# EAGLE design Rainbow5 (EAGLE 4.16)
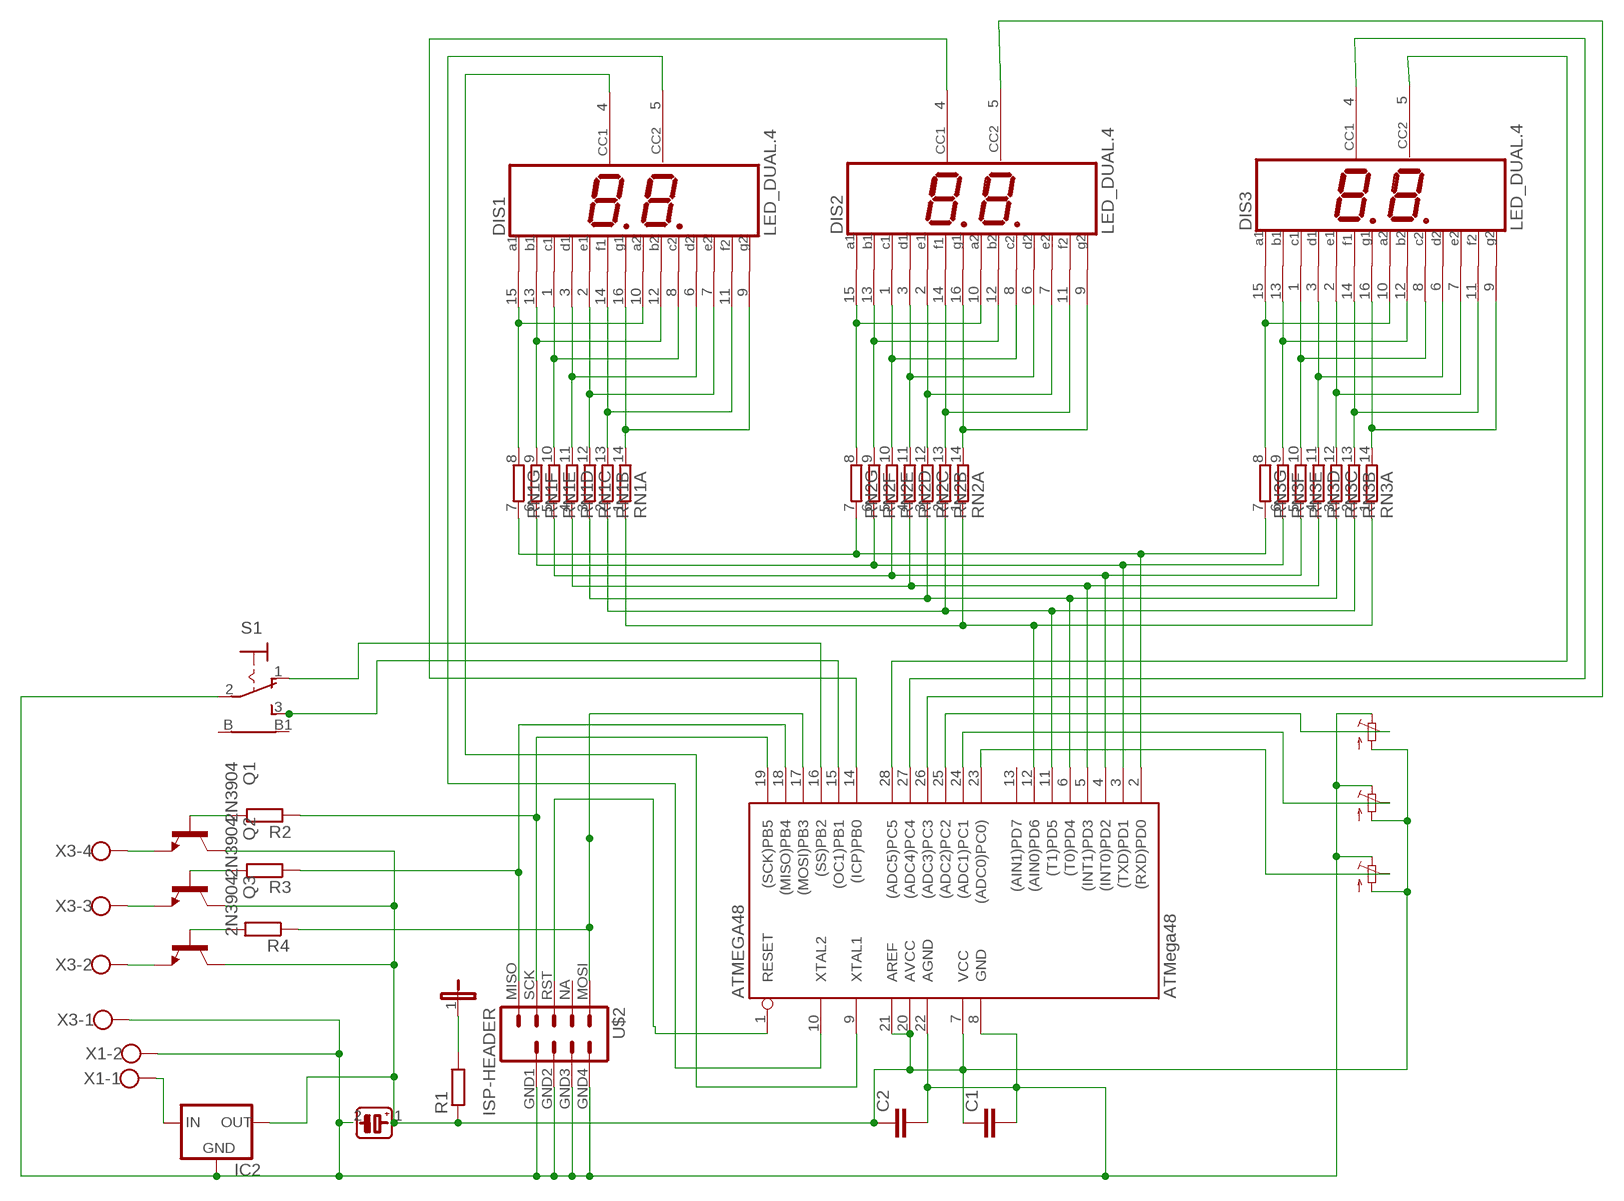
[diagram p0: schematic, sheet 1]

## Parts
ATMEGA48  ATMega48  AT90S4433P  [DIL28-3]
C1  C-EU025-024X044  [C025-024X044]
C2  C-EU025-024X044  [C025-024X044]
DIS1  LED_DUAL.4  [LED_DUAL.4]
DIS2  LED_DUAL.4  [LED_DUAL.4]
DIS3  LED_DUAL.4  [LED_DUAL.4]
IC2  78MXXS  [78MXXS]
Q1  2N3904  [TO92]
Q2  2N3904  [TO92]
Q3  2N3904  [TO92]
R1  R-EU_0204/7  [0204/7]
R2  R-EU_0204/7  [0204/7]
R3  R-EU_0204/7  [0204/7]
R4  R-EU_0204/7  [0204/7]
RN1  7R-N  [DIL14]
RN2  7R-N  [DIL14]
RN3  7R-N  [DIL14]
S1  9070-1W  [9070-1W]
U$1  CAPACITOR_TANTALUM_RADIAL_10UF  [CAPACITOR_TANTALUM_RADIAL_10UF]
U$2  ISP-HEADER  [ISP-HEADER]
U$3  JUMPER1  [JUMPER1]
U$13  POTENTIOMETER_VERTICAL_PCB_.25  [POTENTIOMETER_VERTICAL_PCB_.25]
U$14  POTENTIOMETER_VERTICAL_PCB_.25  [POTENTIOMETER_VERTICAL_PCB_.25]
U$15  POTENTIOMETER_VERTICAL_PCB_.25  [POTENTIOMETER_VERTICAL_PCB_.25]
X1  W237-102  [W237-102]
X3  W237-4  [W237-4]

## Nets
N$1: DIS1.10(A2) DIS1.15(A1) RN1.8
N$2: DIS1.12(B2) DIS1.13(B1) RN1.9
N$3: DIS1.1(C1) DIS1.8(C2) RN1.10
N$4: DIS1.3(D1) DIS1.6(D2) RN1.11
N$5: DIS1.2(E1) DIS1.7(E2) RN1.12
N$6: DIS1.11(F2) DIS1.14(F1) RN1.13
N$7: ATMEGA48.19((SCK)PB5) R2.1 U$2.SCK
N$8: DIS2.10(A2) DIS2.15(A1) RN2.8
N$9: DIS2.12(B2) DIS2.13(B1) RN2.9
N$10: DIS2.1(C1) DIS2.8(C2) RN2.10
N$11: DIS2.3(D1) DIS2.6(D2) RN2.11
N$12: DIS2.2(E1) DIS2.7(E2) RN2.12
N$13: DIS2.11(F2) DIS2.14(F1) RN2.13
N$14: ATMEGA48.18((MISO)PB4) R3.1 U$2.MISO
N$15: ATMEGA48.2((RXD)PD0) RN1.7 RN2.7 RN3.7
N$16: DIS3.1(C1) DIS3.8(C2) RN3.10
N$17: ATMEGA48.7(VCC) ATMEGA48.20(AVCC) ATMEGA48.21(AREF) C1.1 C2.1 IC2.OUT Q1.1(C) Q2.1(C) Q3.1(C) R1.1 U$1.1 U$13.1 U$14.1 U$15.1
N$18: DIS1.9(G2) DIS1.16(G1) RN1.14
N$19: R1.2 U$3.1
N$20: DIS2.9(G2) DIS2.16(G1) RN2.14
N$21: ATMEGA48.3((TXD)PD1) RN1.6 RN2.6 RN3.6
N$22: DIS3.10(A2) DIS3.15(A1) RN3.8
N$23: DIS3.12(B2) DIS3.13(B1) RN3.9
N$24: ATMEGA48.4((INT0)PD2) RN1.5 RN2.5 RN3.5
N$25: DIS3.3(D1) DIS3.6(D2) RN3.11
N$26: DIS3.2(E1) DIS3.7(E2) RN3.12
N$27: DIS3.11(F2) DIS3.14(F1) RN3.13
N$28: DIS3.9(G2) DIS3.16(G1) RN3.14
N$29: ATMEGA48.5((INT1)PD3) RN1.4 RN2.4 RN3.4
N$30: ATMEGA48.6((T0)PD4) RN1.3 RN2.3 RN3.3
N$31: ATMEGA48.11((T1)PD5) RN1.2 RN2.2 RN3.2
N$32: ATMEGA48.8(GND) ATMEGA48.22(AGND) C1.2 C2.2 IC2.GND S1.2(P) U$1.2 U$2.GND1 U$2.GND2 U$2.GND3 U$2.GND4 U$13.3 U$14.3 U$15.3 X1.2 X3.1
N$33: Q1.3(E) X3.4
N$34: ATMEGA48.25((ADC2)PC2) U$13.2
N$35: ATMEGA48.12((AIN0)PD6) RN1.1 RN2.1 RN3.1
N$36: ATMEGA48.24((ADC1)PC1) U$14.2
N$37: ATMEGA48.23((ADC0)PC0)) U$15.2
N$38: ATMEGA48.9(XTAL1) DIS1.4(CC1)
N$39: ATMEGA48.10(XTAL2) DIS1.5(CC2)
N$40: ATMEGA48.14((ICP)PB0) DIS2.4(CC1)
N$41: ATMEGA48.26((ADC3)PC3) DIS2.5(CC2)
N$42: ATMEGA48.27((ADC4)PC4) DIS3.4(CC1)
N$43: ATMEGA48.28((ADC5)PC5) DIS3.5(CC2)
N$44: ATMEGA48.15((OC1)PB1) S1.3(S)
N$45: ATMEGA48.16((SS)PB2) S1.1(O)
N$46: ATMEGA48.17((MOSI)PB3) R4.1 U$2.MOSI
N$47: ATMEGA48.1(RESET) U$2.RST(RESET)
N$48: Q2.3(E) X3.3
N$49: Q3.3(E) X3.2
N$50: Q1.2(B) R2.2
N$51: Q2.2(B) R3.2
N$52: Q3.2(B) R4.2
N$53: IC2.IN X1.1
Unconnected: ATMEGA48.13((AIN1)PD7) S1.B S1.B1 U$2.NA

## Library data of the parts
ATMEGA48 = atmel:AT90S4433: MICROCONTROLLER 4 Kbytes FLASH 128 bytes SRAM 256 bytes EEPROM UART 6-channel 10 bit ADC
C1 C2 = rcl:C-EU: CAPACITOR, European symbol
DIS1-DIS3 = Williams:LED_DUAL.4: LED DISPLAY 2-Digit, 7 segment, decimal point right, .4"
IC2 = v-reg:78MXXS: VOLTAGE REGULATOR
Q1-Q3 = transistor-npn:2N3904: NPN Transistor
R1-R4 = rcl:R-EU_: RESISTOR, European symbol
RN1-RN3 = resistor-dil:7R-N: DIL RESISTOR
S1 = SWITCH:9070-1W: TOGGLE SWITCH Marquardt
U$1 = Williams:CAPACITOR_TANTALUM_RADIAL_10UF
U$2 = Williams:ISP-HEADER
U$3 = Williams:JUMPER1
U$13-U$15 = Williams:POTENTIOMETER_VERTICAL_PCB_.25
X1 = con-wago-500:W237-102: WAGO SCREW CLAMP
X3 = con-wago-500:W237-4: WAGO SCREW CLAMP

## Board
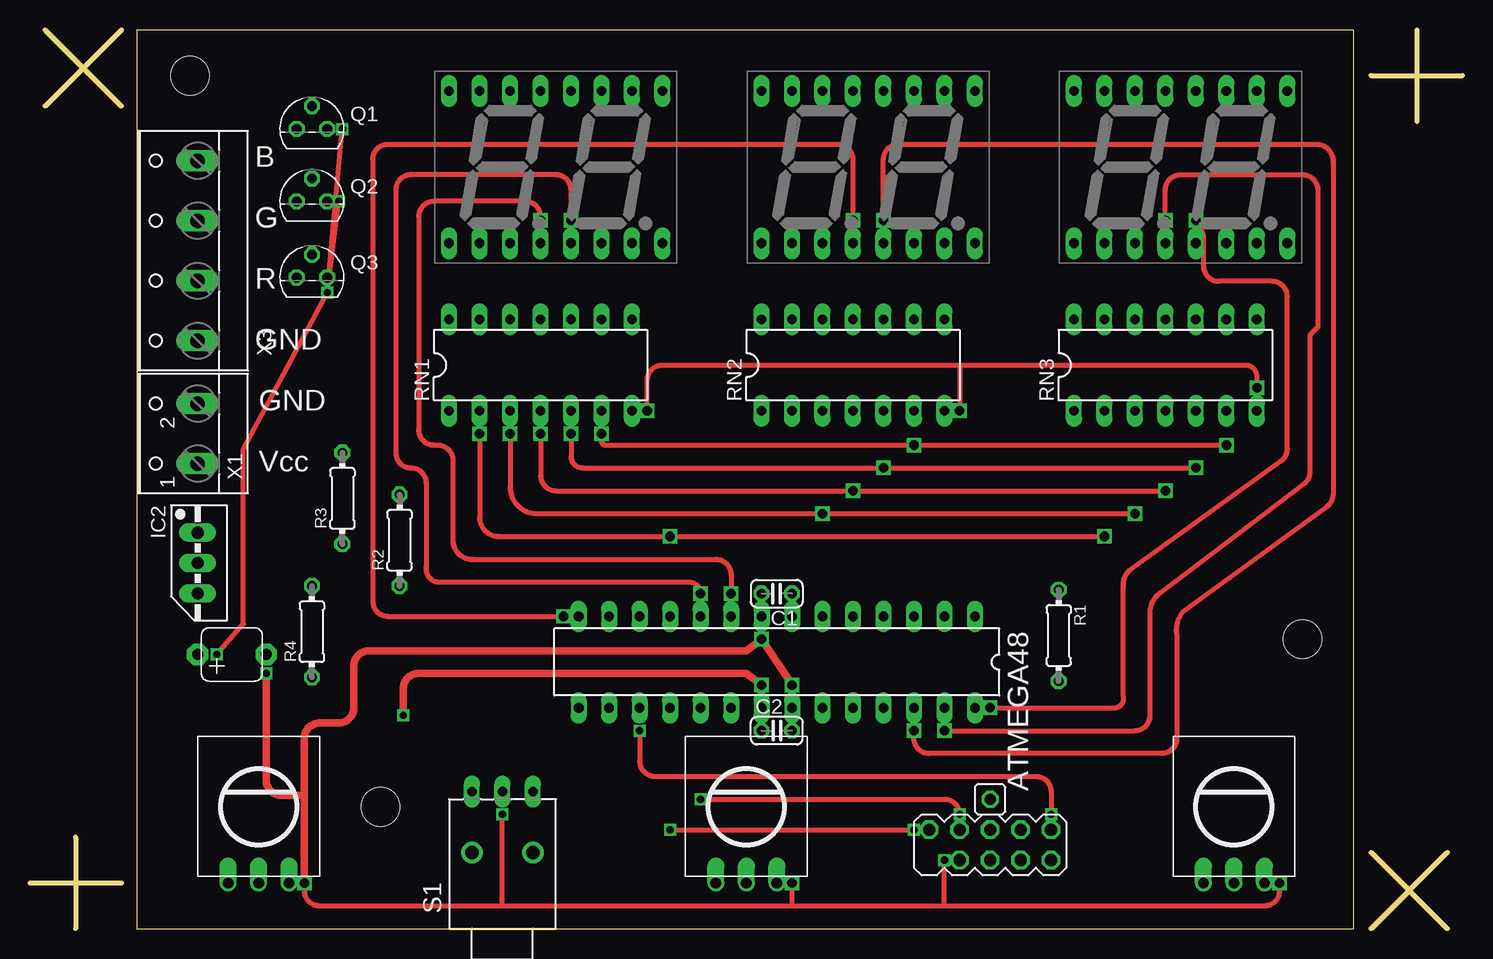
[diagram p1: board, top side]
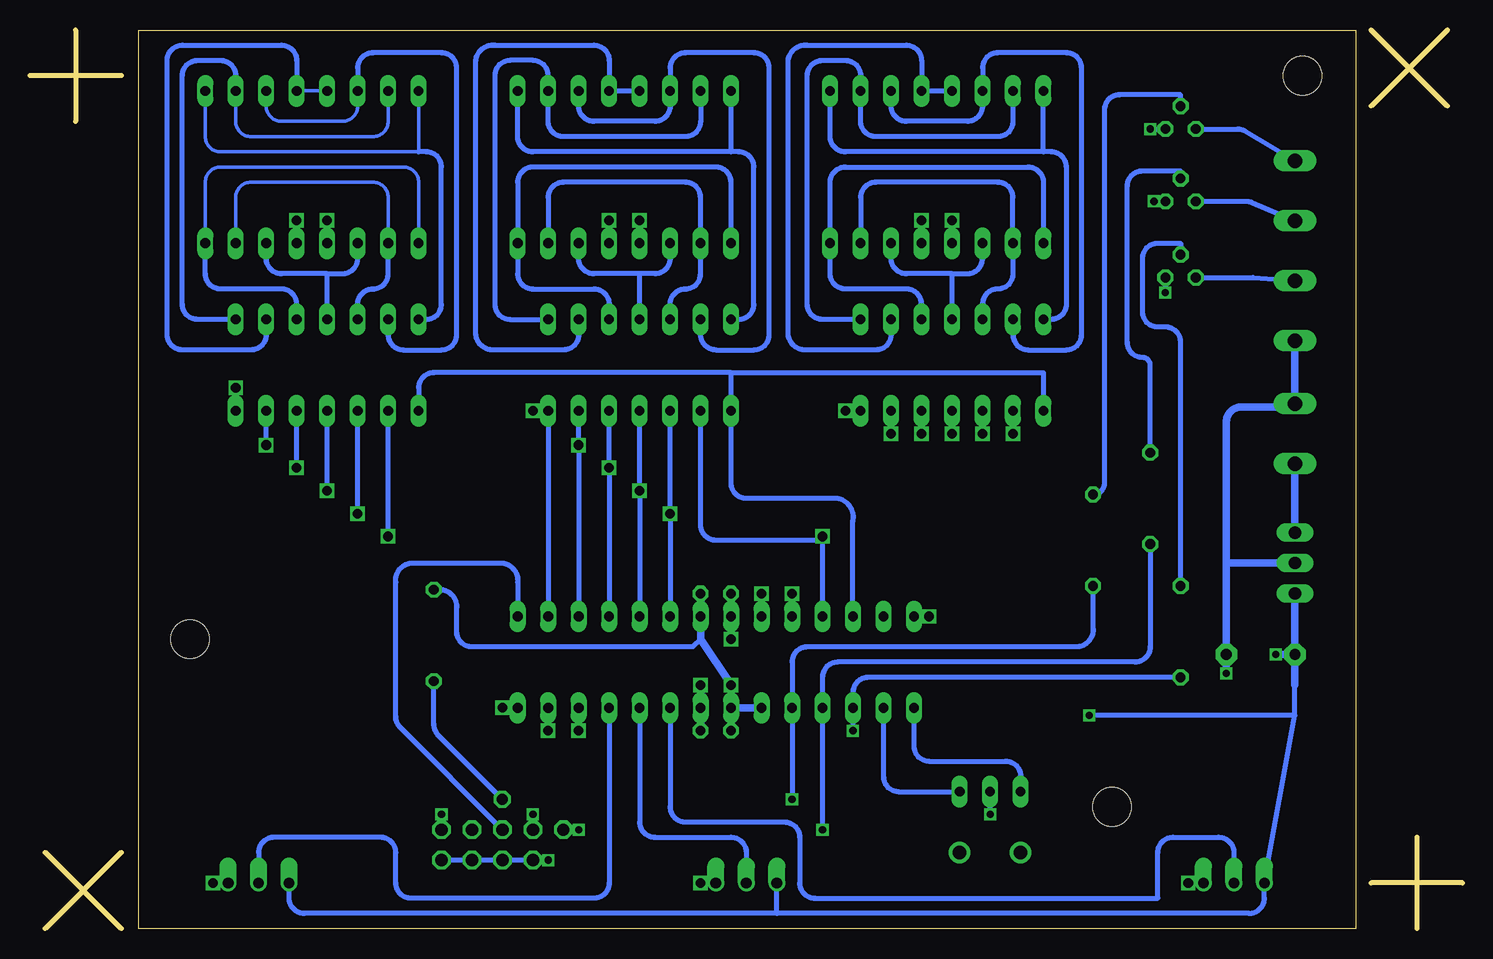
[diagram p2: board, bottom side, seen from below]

Size 119.38 x 74.93 mm. Coordinates in mm from the lower left corner, seen from the top.
Outline: 1.27,74.93 7.62,68.58
Outline: 1.27,68.58 7.62,74.93
Outline: 111.76,6.35 118.11,0
Outline: 111.76,0 118.11,6.35
Outline: 0,3.81 7.62,3.81
Outline: 3.81,7.62 3.81,0
Outline: 115.57,74.93 115.57,67.31
Outline: 111.76,71.12 119.38,71.12
Outline: 8.9,0.01 110.33,0.01 110.33,74.92 8.9,74.92 8.9,0.01
Copper layers (1*16): Top 0.035mm / dielectric 1.5mm / Bottom 0.035mm
Design rules "default": minimum track width 10mil, minimum drill 24mil, track to track 8mil, track to pad 8mil, pad to pad 8mil, via to via 8mil, smd to smd 8mil, copper to edge 40mil, drill to drill 8mil, minimum pad ring 10mil, minimum via ring 8mil, stop-mask expansion 4mil, vias tented up to drill 0mil, thermal gap 10mil
Holes 3.2 mm at 29.21,10.16 106.05,24.13 13.34,71.12

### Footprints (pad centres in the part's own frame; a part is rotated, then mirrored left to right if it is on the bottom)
DIL28-3 = drill 0.813 long: 1 -16.51,-3.81; 2 -13.97,-3.81; 3 -11.43,-3.81; 4 -8.89,-3.81; 5 -6.35,-3.81; 6 -3.81,-3.81; 7 -1.27,-3.81; 8 1.27,-3.81; 9 3.81,-3.81; 10 6.35,-3.81; 11 8.89,-3.81; 12 11.43,-3.81; 13 13.97,-3.81; 14 16.51,-3.81; 15 16.51,3.81; 16 13.97,3.81; 17 11.43,3.81; 18 8.89,3.81; 19 6.35,3.81; 20 3.81,3.81; 21 1.27,3.81; 22 -1.27,3.81; 23 -3.81,3.81; 24 -6.35,3.81; 25 -8.89,3.81; 26 -11.43,3.81; 27 -13.97,3.81; 28 -16.51,3.81
C025-024X044 = drill 0.813 octagon: 1 -1.27,0; 2 1.27,0
LED_DUAL.4 = drill 0.813 long: 1 -8.89,-6.35; 2 -6.35,-6.35; 3 -3.81,-6.35; 4 -1.27,-6.35; 5 1.27,-6.35; 6 3.81,-6.35; 7 6.35,-6.35; 8 8.89,-6.35; 9 8.89,6.35; 10 6.35,6.35; 11 3.81,6.35; 12 1.27,6.35; 13 -1.27,6.35; 14 -3.81,6.35; 15 -6.35,6.35; 16 -8.89,6.35
78MXXS = drill 1.016 long: GND 0,-2.54; IN -2.54,-2.54; OUT 2.54,-2.54
TO92 = drill 0.813 octagon: 1 1.27,0; 2 0,1.905; 3 -1.27,0
0204/7 = drill 0.813 octagon: 1 -3.81,0; 2 3.81,0
DIL14 = drill 0.813 long: 1 -7.62,-3.81; 2 -5.08,-3.81; 3 -2.54,-3.81; 4 0,-3.81; 5 2.54,-3.81; 6 5.08,-3.81; 7 7.62,-3.81; 8 7.62,3.81; 9 5.08,3.81; 10 2.54,3.81; 11 0,3.81; 12 -2.54,3.81; 13 -5.08,3.81; 14 -7.62,3.81
9070-1W = drill 0.813 long: 1 5.08,-2.54; 2 5.08,0; 3 5.08,2.54 | drill 1.118 pad 1.778 round: B 0,-2.54; B1 0,2.54
CAPACITOR_TANTALUM_RADIAL_10UF = drill 0.9 pad 1.778 octagon: 1 -2.54,0; 2 3.175,0
ISP-HEADER = drill 1.016 octagon: GND1 -2.54,-1.27; GND2 0,-1.27; GND3 2.54,-1.27; GND4 5.08,-1.27; MISO -5.08,1.27; MOSI 5.08,1.27; NA 2.54,1.27; RST 0,1.27; SCK -2.54,1.27
JUMPER1 = drill 0.914 octagon: 1 0,0
POTENTIOMETER_VERTICAL_PCB_.25 = drill 0.9 pad 1.422 offset: 1 -2.54,-6.35; 2 0,-6.35; 3 2.54,-6.35
W237-102 = drill 1.194 long: 1 -2.5,-1.27; 2 2.5,-1.27
W237-4 = drill 1.194 long: 1 -7.5,-1.27; 2 -2.5,-1.27; 3 2.5,-1.27; 4 7.5,-1.27

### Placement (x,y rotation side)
ATMEGA48  62.23,22.23 180 top
C1  62.23,27.94 180 top
C2  62.23,16.51 0 top
DIS1  43.81,63.5 0 top
DIS2  69.85,63.5 0 top
DIS3  95.89,63.5 0 top
IC2  16.51,30.48 270 top
Q1  23.5,66.67 0 top
Q2  23.5,60.64 0 top
Q3  23.5,54.29 0 top
R1  85.72,24.45 270 top
R2  30.8,32.38 90 top
R3  26.04,35.88 90 top
R4  23.5,24.77 90 top
RN1  42.55,46.99 0 top
RN2  68.58,46.99 0 top
RN3  94.61,46.99 0 top
S1  39.37,6.35 90 top
U$1  16.51,22.86 0 top
U$2  80.01,6.99 0 top
U$3  80.01,10.79 90 top
U$13  100.33,10.16 0 top
U$14  59.69,10.16 0 top
U$15  19.05,10.16 0 top
X1  12.7,41.27 90 top
X3  12.7,56.52 90 top

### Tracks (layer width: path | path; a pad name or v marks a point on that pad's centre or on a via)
N$1
  Bottom 0.406: RN1.8 53.34,50.8 arc90 54.61,52.07 54.61,71.12 arc90 53.34,72.39 51.44,72.39 arc90 50.16,71.12 DIS1.10 50.16,67.31 arc-90 48.9,66.04 38.73,66.04 arc-90 37.47,67.31 DIS1.15
N$2
  Bottom 0.406: DIS1.13 DIS1.12 45.09,72.39 arc-90 46.36,73.66 54.61,73.66 arc-90 56.2,72.39 56.2,49.53 arc-90 54.61,48.26 48.9,48.26 arc-90 47.62,49.53 RN1.9
N$3
  Bottom 0.406: DIS1.1 34.92,62.23 arc-90 36.2,63.5 51.44,63.5 arc-90 52.7,62.23 DIS1.8 52.7,54.61 arc-90 51.44,53.34 46.36,53.34 arc90 45.09,52.07 RN1.10
N$4
  Bottom 0.406: 42.55,54.61 41.27,54.61 arc-90 40,55.88 DIS1.3 | 42.55,54.61 46.36,54.61 arc90 47.62,55.88 DIS1.6 | RN1.11 42.55,54.61
N$5
  Bottom 0.406: DIS1.7 50.16,60.96 arc90 48.9,62.23 38.73,62.23 arc90 37.47,60.96 DIS1.2 37.47,54.61 arc90 38.73,53.34 arc-90 40,52.07 RN1.12
N$6
  Bottom 0.406: DIS1.11 47.62,68.58 arc-90 46.36,67.31 41.27,67.31 arc-90 40,68.58 DIS1.14 40,71.75 arc90 38.73,73.03 33.02,73.03 arc90 31.75,71.75 31.75,49.53 arc90 33.02,48.26 36.2,48.26 arc90 37.47,49.53 RN1.13
N$7  (via drill 0.6)
  Top 0.406: v55.88,10.79 76.2,10.79 arc-90 v77.47,9.53
  Bottom 0.406: v55.88,10.79 ATMEGA48.19 55.88,22.23 arc90 54.61,23.5 32.07,23.5 arc-90 30.8,25.08 R2.1 | v77.47,9.53 U$2.SCK
N$8
  Bottom 0.406: DIS2.15 63.5,67.31 arc90 64.77,66.04 74.93,66.04 arc90 76.2,67.31 DIS2.10 76.2,71.12 arc-90 77.47,72.39 79.38,72.39 arc-90 80.64,71.12 80.64,52.07 arc-90 79.38,50.8 RN2.8
N$9
  Bottom 0.406: DIS2.13 DIS2.12 71.12,72.39 arc-90 72.39,73.66 80.64,73.66 arc-90 82.23,72.39 82.23,49.53 arc-90 80.64,48.26 74.93,48.26 arc-90 73.66,49.53 RN2.9
N$10
  Bottom 0.406: DIS2.1 60.96,62.23 arc-90 62.23,63.5 77.47,63.5 arc-90 78.74,62.23 DIS2.8 78.74,54.61 arc-90 77.47,53.34 72.39,53.34 arc90 71.12,52.07 RN2.10
N$11
  Bottom 0.406: DIS2.3 66.04,55.88 arc90 67.31,54.61 68.58,54.61 | 68.58,54.61 72.39,54.61 arc90 73.66,55.88 DIS2.6 | RN2.11 68.58,54.61
N$12
  Bottom 0.406: DIS2.7 76.2,60.96 arc90 74.93,62.23 64.77,62.23 arc90 63.5,60.96 DIS2.2 63.5,54.61 arc90 64.77,53.34 arc-90 66.04,52.07 RN2.12
N$13
  Bottom 0.406: DIS2.11 73.66,68.58 arc-90 72.39,67.31 67.31,67.31 arc-90 66.04,68.58 DIS2.14 66.04,71.75 arc90 64.77,73.03 59.05,73.03 arc90 57.79,71.75 57.79,49.53 arc90 59.05,48.26 62.23,48.26 arc90 63.5,49.53 RN2.13
N$14  (via drill 0.6)
  Top 0.406: v53.34,8.26 v73.66,8.26
  Bottom 0.406: v53.34,8.26 ATMEGA48.18 53.34,20.95 arc90 52.07,22.23 27.3,22.23 arc-90 26.04,23.5 R3.1 | v73.66,8.26 U$2.MISO
N$15  (via drill 0.8)
  Top 0.406: 77.47,46.99 v77.47,43.18 | 77.47,46.99 101.28,46.99 arc-90 102.23,46.04 v102.23,45.09 | v51.44,43.18 51.44,45.72 arc-90 52.7,46.99 77.47,46.99
  Bottom 0.406: v77.47,43.18 RN2.7 ATMEGA48.2 | RN1.7 v51.44,43.18 | v102.23,45.09 RN3.7
N$16
  Bottom 0.305: DIS3.1 87,62.23 arc-90 88.27,63.5 103.5,63.5 arc-90 104.78,62.23 DIS3.8
  Bottom 0.406: RN3.10 97.16,52.07 arc-90 98.42,53.34 103.5,53.34 arc90 104.78,54.61 DIS3.8
N$17  (via drill 0.6, 0.8)
  Top 0.406: v15.56,22.86 17.78,25.4 17.78,40.01 v24.77,53.02 | v24.77,53.02 v25.72,60.64 | v24.77,53.02 v26.04,66.67
  Top 0.61: v60.96,20.32 59.69,21.27 32.39,21.27 arc90 31.12,20 v31.12,17.78
  Bottom 0.406: 57.15,1.27 17.78,1.27 arc-90 16.51,2.54 U$15.1 13.97,17.78 | 57.15,1.27 U$14.1 | 57.15,1.27 96.52,1.27 arc90 97.79,2.54 U$13.1 | ATMEGA48.7 63.5,26.67 | R1.1 85.09,28.26 arc90 83.82,26.67 83.82,24.77 arc-90 82.55,23.5 64.13,23.5 63.5,24.13 | Q3.1 v24.77,53.02 | v25.72,60.64 Q2.1 | v26.04,66.67 Q1.1 | 13.97,17.78 13.97,20.32 | 13.97,17.78 v31.12,17.78
  Bottom 0.61: ATMEGA48.21 C2.1 | ATMEGA48.21 ATMEGA48.20 | ATMEGA48.21 v60.96,20.32 63.5,24.13 ATMEGA48.7 C1.1 | v15.56,22.86 U$1.1 13.97,20.32 IC2.OUT
N$18
  Bottom 0.406: 34.92,64.77 DIS1.16 | 34.92,64.77 51.44,64.77 arc90 52.7,66.04 DIS1.9 | 34.92,64.77 34.29,64.77 arc90 33.02,63.5 33.02,52.07 arc90 34.29,50.8 RN1.14
N$19
  Bottom 0.406: U$3.1 85.35,16.14 arc45 85.72,17.04 R1.2
N$20
  Bottom 0.406: 60.96,64.77 DIS2.16 | 60.96,64.77 77.47,64.77 arc90 78.74,66.04 DIS2.9 | RN2.14 60.33,50.8 arc-90 59.05,52.07 59.05,63.5 arc-90 60.33,64.77 60.96,64.77
N$21  (via drill 0.8)
  Top 0.406: v47.62,41.27 47.62,40.64 arc90 47.94,40.32 v73.66,40.32 v99.7,40.32
  Bottom 0.406: ATMEGA48.3 v73.66,40.32 RN2.6 | v47.62,41.27 RN1.6 | v99.7,40.32 RN3.6
N$22
  Bottom 0.305: DIS3.10 102.23,67.31 arc-90 100.97,66.04 90.81,66.04 arc-90 89.53,67.31 DIS3.15
  Bottom 0.406: RN3.8 105.41,50.8 arc90 106.68,52.07 106.68,71.12 arc90 105.41,72.39 103.5,72.39 arc90 102.23,71.12 DIS3.10
N$23
  Bottom 0.305: DIS3.13 DIS3.12
  Bottom 0.406: RN3.9 99.7,49.53 arc90 100.97,48.26 106.68,48.26 arc90 107.95,49.53 107.95,72.39 arc90 106.68,73.66 98.42,73.66 arc90 97.16,72.39 DIS3.12
N$24  (via drill 0.8)
  Top 0.406: v45.09,41.27 45.09,39.37 arc90 46.04,38.42 v71.12,38.42 v97.16,38.42
  Bottom 0.406: ATMEGA48.4 v71.12,38.42 RN2.5 | v45.09,41.27 RN1.5 | v97.16,38.42 RN3.5
N$25
  Bottom 0.406: RN3.11 94.61,54.61 | 94.61,54.61 93.34,54.61 arc-90 92.08,55.88 DIS3.3 | 94.61,54.61 98.42,54.61 arc90 99.7,55.88 DIS3.6
N$26
  Bottom 0.305: DIS3.2 89.53,60.96 arc-90 90.81,62.23 100.97,62.23 arc-90 102.23,60.96 DIS3.7
  Bottom 0.406: RN3.12 92.08,52.07 arc90 90.81,53.34 arc-90 89.53,54.61 DIS3.2
N$27
  Bottom 0.305: DIS3.14 92.08,68.58 arc90 93.34,67.31 98.42,67.31 arc90 99.7,68.58 DIS3.11
  Bottom 0.406: RN3.13 89.53,49.53 arc-90 88.27,48.26 85.09,48.26 arc-90 83.82,49.53 83.82,71.75 arc-90 85.09,73.03 90.81,73.03 arc-90 92.08,71.75 DIS3.14
N$28
  Bottom 0.305: DIS3.16 87,64.77 103.5,64.77 arc90 104.78,66.04 DIS3.9
  Bottom 0.406: RN3.14 86.36,50.8 arc-90 85.09,52.07 85.09,63.5 arc-90 86.36,64.77 87,64.77
N$29  (via drill 0.8)
  Top 0.406: v42.55,41.27 42.55,37.78 arc90 43.81,36.51 v68.58,36.51 v94.61,36.51
  Bottom 0.406: ATMEGA48.5 v68.58,36.51 RN2.4 | v42.55,41.27 RN1.4 | v94.61,36.51 RN3.4
N$30  (via drill 0.8)
  Top 0.406: v40,41.27 40,36.83 arc90 42.23,34.61 v66.04,34.61 v92.08,34.61
  Bottom 0.406: ATMEGA48.6 v66.04,34.61 RN2.3 | v40,41.27 RN1.3 | v92.08,34.61 RN3.3
N$31  (via drill 0.8)
  Top 0.406: v37.47,41.27 37.47,34.29 arc90 39.05,32.7 v53.34,32.7 v89.53,32.7
  Bottom 0.406: RN2.2 63.5,33.66 arc-90 62.23,32.38 53.34,32.38 v53.34,32.7 ATMEGA48.11 | v37.47,41.27 RN1.2 | v89.53,32.7 RN3.2
N$32  (via drill 0.6, 0.8)
  Top 0.406: v22.86,3.81 22.86,3.17 arc90 24.13,1.91 39.37,1.91 | 39.37,1.91 63.5,1.91 | 63.5,1.91 v63.5,3.81 | 63.5,1.91 76.2,1.91 | 76.2,1.91 102.87,1.91 arc90 104.14,3.17 v104.14,3.81 | 39.37,1.91 v39.37,9.53 | 76.2,1.91 v76.2,5.71
  Top 0.61: v63.5,20.32 v60.96,24.13 59.69,23.18 28.26,23.18 arc90 26.99,21.91 26.99,18.41 arc-90 25.72,17.14 24.13,17.14 arc90 22.86,15.88 22.86,11.11 | 22.86,11.11 20.95,11.11 arc-90 19.69,12.38 v19.69,21.27 | v22.86,3.81 22.86,11.11
  Bottom 0.406: v22.86,3.81 U$15.3 | v63.5,3.81 U$14.3 | v104.14,3.81 U$13.3 | v39.37,9.53 S1.2 | U$2.GND4 U$2.GND3 U$2.GND2 U$2.GND1 v76.2,5.71
  Bottom 0.61: C2.2 ATMEGA48.22 v63.5,20.32 | C1.2 ATMEGA48.8 v60.96,24.13 | X3.1 X1.2 13.97,43.5 18.41,43.5 arc-90 19.69,42.23 19.69,30.48 | v19.69,21.27 U$1.2 19.69,30.48 | 19.69,30.48 IC2.GND
N$33
  Bottom 0.406: Q1.3 18.77,66.67 arc31 18.11,66.5 X3.4
N$34
  Bottom 0.406: ATMEGA48.25 71.12,3.81 arc90 72.39,2.54 87.63,2.54 arc90 88.9,3.81 88.9,6.35 arc-90 90.17,7.62 99.06,7.62 arc-90 100.33,6.35 U$13.2
N$35
  Bottom 0.406: RN1.1 34.92,46.35 60.96,46.35 | 60.96,46.35 RN2.1 60.96,37.15 arc-90 59.69,35.88 52.07,35.88 arc90 50.8,33.97 ATMEGA48.12 | 60.96,46.35 85.72,46.35 arc-90 87,45.09 RN3.1
N$36
  Bottom 0.406: ATMEGA48.24 68.58,8.89 arc-90 67.31,7.62 60.96,7.62 arc90 59.69,6.35 U$14.2
N$37
  Bottom 0.406: ATMEGA48.23 66.04,10.16 arc-90 64.77,8.89 56.52,8.89 arc90 55.24,7.62 55.24,3.81 arc-90 53.98,2.54 25.4,2.54 25.4,6.35 arc90 24.13,7.62 20.32,7.62 arc90 19.05,6.35 U$15.2
N$38  (via drill 0.8)
  Top 0.406: v42.55,59.05 42.55,59.37 arc90 41.27,60.64 33.66,60.64 arc90 32.39,59.37 32.39,41.59 arc90 33.66,40.32 33.97,40.32 arc-90 35.24,39.05 35.24,32.38 arc90 36.83,30.8 57.15,30.8 arc-90 58.42,29.53 v58.42,27.94
  Bottom 0.406: v42.55,59.05 DIS1.4 | v58.42,27.94 ATMEGA48.9
N$39  (via drill 0.8)
  Top 0.406: v45.09,59.05 45.09,61.59 arc90 43.81,62.87 31.75,62.87 arc90 30.48,61.59 30.48,39.69 arc90 31.75,38.42 arc-90 33.02,37.15 33.02,30.16 arc90 33.97,28.89 54.93,28.89 arc-90 v55.88,27.94
  Bottom 0.406: DIS1.5 v45.09,59.05 | v55.88,27.94 ATMEGA48.10
N$40  (via drill 0.8)
  Top 0.406: v68.58,59.05 68.58,64.14 arc90 67.31,65.41 29.84,65.41 arc90 28.57,64.14 28.57,27.3 arc90 29.84,26.04 v44.45,26.04
  Bottom 0.406: v68.58,59.05 DIS2.4 | v44.45,26.04 ATMEGA48.14
N$41  (via drill 0.8)
  Top 0.406: v71.12,59.05 71.12,64.14 arc-90 72.39,65.41 107.31,65.41 arc-90 108.58,63.82 108.58,36.2 arc-54 108.07,35.18 96.08,26.42 arc54 95.57,24.44 95.57,15.88 arc-90 94.3,14.61 74.93,14.61 arc-90 73.66,15.88 v73.66,16.51
  Bottom 0.406: DIS2.5 v71.12,59.05 | v73.66,16.51 ATMEGA48.26
N$42  (via drill 0.8)
  Top 0.406: v94.61,59.05 94.61,61.59 arc-90 95.89,62.87 106.05,62.87 arc-90 107.31,61.59 107.31,50.16 106.68,49.53 106.68,38.11 arc-54 106.16,37.09 94.19,28 arc54 93.34,26.34 93.34,17.78 arc-90 92.08,16.51 v76.2,16.51
  Bottom 0.406: DIS3.4 v94.61,59.05 | v76.2,16.51 ATMEGA48.27
N$43  (via drill 0.8)
  Top 0.406: v97.16,59.05 97.16,59.37 97.7,58.01 arc-22 97.79,57.54 97.79,55.24 arc90 99.06,53.98 103.5,53.98 arc-90 104.78,52.7 104.78,40.02 arc-54 104.24,38.99 91.65,29.91 arc54 91.12,28.56 91.12,19.37 arc-90 90.49,18.41 v80.01,18.41
  Bottom 0.406: DIS3.5 v97.16,59.05 | ATMEGA48.28 v80.01,18.41
N$44
  Bottom 0.406: ATMEGA48.15 45.72,15.24 arc-90 44.45,13.97 38.1,13.97 arc90 36.83,12.7 S1.3
N$45
  Bottom 0.406: ATMEGA48.16 48.26,12.7 arc-90 46.99,11.43 S1.1
N$46  (via drill 0.6)
  Top 0.406: v50.8,16.51 50.8,13.97 arc90 52.07,12.7 83.82,12.7 arc-90 85.09,11.43 v85.09,9.53
  Bottom 0.406: v50.8,16.51 ATMEGA48.17 50.8,19.68 arc90 49.53,20.95 R4.1 | v85.09,9.53 U$2.MOSI
N$47
  Bottom 0.406: ATMEGA48.1 78.74,28.89 arc-90 80.01,30.48 87.63,30.48 arc-90 88.9,28.89 88.9,17.67 arc-45 88.53,16.77 U$2.RST
N$48
  Bottom 0.406: Q2.3 18.04,60.64 arc23 17.54,60.54 X3.3
N$49
  Bottom 0.406: Q3.3 17.46,54.29 X3.2
N$50
  Bottom 0.406: Q1.2 23.5,69.53 28.57,69.53 arc-90 29.84,68.26 29.84,37.15 arc90 R2.2
N$51
  Bottom 0.406: R3.2 26.04,46.99 arc-90 26.67,47.62 arc90 27.94,48.9 27.94,61.91 arc90 26.67,63.18 23.5,63.18 Q2.2
N$52
  Bottom 0.406: R4.2 23.5,48.9 arc-90 24.77,50.16 25.4,50.16 arc90 26.67,51.44 26.67,55.88 arc90 25.4,57.15 23.5,57.15 Q3.2
N$53
  Bottom 0.61: X1.1 IC2.IN

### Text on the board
tPlace: B | G | R | GND | GND | Vcc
